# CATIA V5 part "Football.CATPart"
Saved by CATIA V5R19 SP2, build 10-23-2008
Part number: Ball
Bounding box of the stored display mesh (mm): x -250 to 250, y -476.463 to 23.007, z -250 to 250
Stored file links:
  D:\Catia\Football.CATPart
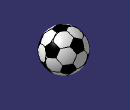
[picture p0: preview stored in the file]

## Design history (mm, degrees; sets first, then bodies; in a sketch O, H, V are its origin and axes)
AxisSystem1: origin (0, 0, 0), X (1, 0, 0), Y (0, 1, 0), Z (0, 0, 1)
Set1 "Ball"
  DatumSurface1 to DatumSurface32
Body1 (main body)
